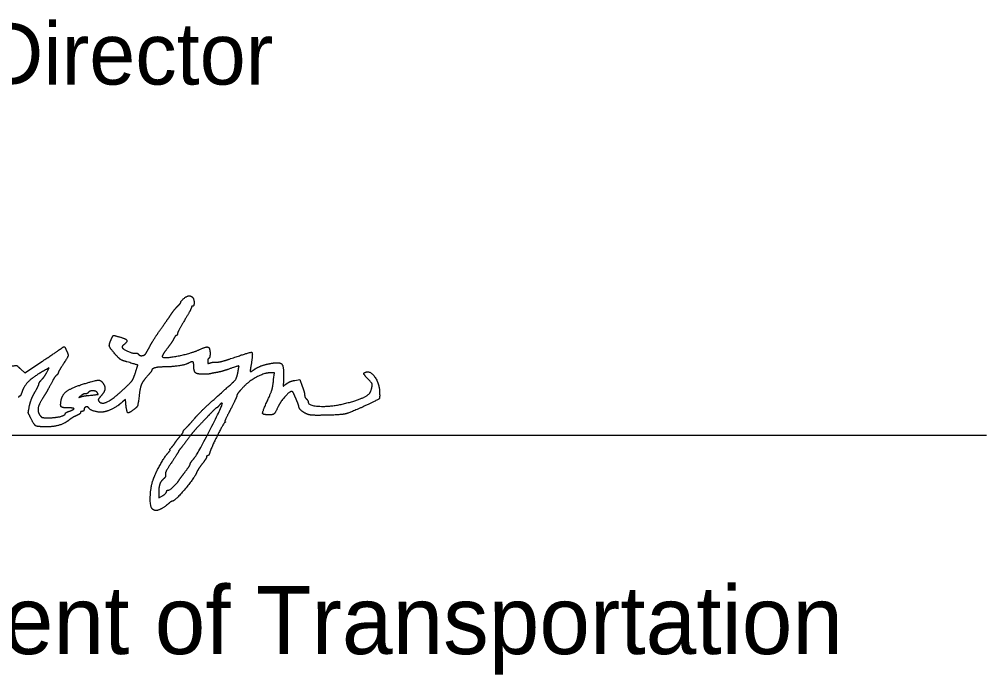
# Model space of a CAD drawing. Extents: x -3.6 to 34, y 0 to 32.8.
# Drawn here: x 26.697 to 28.884, y 4.004 to 5.485 of the extents above; entities that cross this region are included whole.
import ezdxf

# ---------------------------------------------------------------- set-up
doc = ezdxf.new("R2010")
doc.units = 0
doc.layers.add('SH_Data', color=7, linetype='Continuous')
doc.layers.add('SH_Text', color=7, linetype='Continuous')

msp = doc.modelspace()

# ---------------------------------------------------------------- linework, layer by layer
at = {"layer": 'SH_Data'}
msp.add_line((25.0343, 4.5451), (28.8843, 4.5451), dxfattribs=at)
at = {"layer": 'SH_Text'}
for points in [[(26.7, 4.6941), (26.709, 4.6858), (26.7488, 4.7123)], [(26.7593, 4.6883), (26.7642, 4.6971), (26.7581, 4.6938)], [(27.2717, 4.6708), (27.2734, 4.686), (27.2648, 4.686)], [(27.32, 4.669), (27.3306, 4.6708), (27.3362, 4.6558)], [(26.9372, 4.6183), (26.9365, 4.6258), (26.93, 4.6202)], [(27.0118, 4.4135), (27.0118, 4.4032), (27.02, 4.408)]]:
    msp.add_lwpolyline(points, dxfattribs=at)
for points in [[(27.0619, 4.8457), (27.0619, 4.8488), (27.0764, 4.8601), (27.0805, 4.8602)], [(27.0805, 4.8602), (27.0828, 4.8602), (27.086, 4.8588), (27.0878, 4.8571)], [(27.0878, 4.8571), (27.0916, 4.8533), (27.092, 4.8365), (27.0883, 4.8365)], [(27.0395, 4.8178), (27.0438, 4.8242), (27.0507, 4.8327), (27.0547, 4.8367)], [(27.0547, 4.8367), (27.0587, 4.8407), (27.0619, 4.8447), (27.0619, 4.8457)], [(27.0883, 4.8365), (27.0869, 4.8365), (27.0857, 4.8352), (27.0857, 4.8337)], [(27.0157, 4.7837), (27.0244, 4.796), (27.0352, 4.8114), (27.0395, 4.8178)], [(27.0857, 4.8337), (27.0857, 4.8322), (27.0786, 4.8189), (27.0698, 4.8042)], [(27.0698, 4.8042), (27.0611, 4.7894), (27.054, 4.7758), (27.054, 4.7739)], [(26.9035, 4.7598), (26.9076, 4.7697), (26.911, 4.7708), (26.925, 4.7667)], [(26.9922, 4.7467), (26.9964, 4.7547), (27.007, 4.7713), (27.0157, 4.7837)], [(27.0518, 4.7705), (27.0506, 4.7705), (27.048, 4.7672), (27.046, 4.7632)], [(27.054, 4.7739), (27.054, 4.772), (27.053, 4.7705), (27.0518, 4.7705)], [(26.9142, 4.7274), (26.9016, 4.7418), (26.8991, 4.7492), (26.9035, 4.7598)], [(26.925, 4.7667), (26.9382, 4.7628), (26.9413, 4.756), (26.9329, 4.7496)], [(26.9329, 4.7496), (26.9299, 4.7473), (26.9283, 4.7442), (26.9293, 4.7427)], [(27.046, 4.7632), (27.044, 4.7592), (27.0373, 4.7492), (27.0311, 4.741)], [(26.7488, 4.7123), (26.7707, 4.7269), (26.7901, 4.74), (26.7919, 4.7414)], [(26.7919, 4.7414), (26.7969, 4.7456), (26.7995, 4.7446), (26.8028, 4.7374)], [(26.8028, 4.7374), (26.8076, 4.7268), (26.8066, 4.7223), (26.7953, 4.7048)], [(26.94, 4.7108), (26.9282, 4.7142), (26.9228, 4.7177), (26.9142, 4.7274)], [(26.9293, 4.7427), (26.9323, 4.7385), (26.9542, 4.7295), (26.9593, 4.7304)], [(26.9593, 4.7304), (26.9617, 4.7308), (26.9645, 4.7299), (26.9655, 4.7284)], [(26.9655, 4.7284), (26.9678, 4.7245), (26.9789, 4.7249), (26.982, 4.7289)], [(26.982, 4.7289), (26.9834, 4.7307), (26.988, 4.7387), (26.9922, 4.7467)], [(27.0311, 4.741), (27.0248, 4.7328), (27.0197, 4.7248), (27.0197, 4.7233)], [(27.0197, 4.7233), (27.0197, 4.7175), (27.0853, 4.7296), (27.105, 4.739)], [(27.105, 4.739), (27.1193, 4.7458), (27.1279, 4.7423), (27.1279, 4.7298)], [(27.1279, 4.7298), (27.1279, 4.7248), (27.1267, 4.7199), (27.1253, 4.719)], [(27.1745, 4.718), (27.2189, 4.7333), (27.2254, 4.7315), (27.2209, 4.7052)], [(26.7953, 4.7048), (26.7895, 4.6958), (26.7847, 4.6875), (26.7847, 4.6862)], [(26.9585, 4.6846), (26.9647, 4.7031), (26.9643, 4.7037), (26.94, 4.7108)], [(27.0784, 4.7073), (27.0722, 4.704), (27.039, 4.6992), (27.0226, 4.6992)], [(27.091, 4.7021), (27.091, 4.7102), (27.0869, 4.7119), (27.0784, 4.7073)], [(27.1253, 4.719), (27.1238, 4.7181), (27.1226, 4.715), (27.1226, 4.7121)], [(27.1226, 4.7121), (27.1226, 4.7078), (27.1238, 4.7071), (27.1286, 4.7087)], [(27.1286, 4.7087), (27.1318, 4.7097), (27.1383, 4.7104), (27.1428, 4.7103)], [(27.1428, 4.7103), (27.1474, 4.7101), (27.1616, 4.7136), (27.1745, 4.718)], [(27.2209, 4.7052), (27.2194, 4.6968), (27.2186, 4.6895), (27.2191, 4.689)], [(27.2274, 4.6933), (27.2354, 4.6988), (27.2555, 4.7058), (27.2705, 4.7081)], [(27.2705, 4.7081), (27.2866, 4.7107), (27.295, 4.6992), (27.2942, 4.6759)], [(26.6686, 4.7012), (26.6909, 4.7025), (26.6911, 4.7025), (26.7, 4.6941)], [(26.7581, 4.6938), (26.7324, 4.6801), (26.7073, 4.6573), (26.7028, 4.6436)], [(26.7452, 4.6684), (26.7512, 4.675), (26.754, 4.6789), (26.7593, 4.6883)], [(26.7847, 4.6862), (26.7847, 4.685), (26.783, 4.6826), (26.7808, 4.6808)], [(26.9384, 4.6546), (26.9498, 4.6656), (26.9544, 4.6724), (26.9585, 4.6846)], [(26.9959, 4.6913), (26.9959, 4.6903), (26.9913, 4.6844), (26.9856, 4.6781)], [(27.0226, 4.6992), (27.0099, 4.6992), (26.9959, 4.6951), (26.9959, 4.6913)], [(27.1122, 4.6827), (27.0986, 4.6828), (27.091, 4.6897), (27.091, 4.7021)], [(27.1306, 4.6843), (27.1269, 4.6834), (27.1187, 4.6827), (27.1122, 4.6827)], [(27.1451, 4.6871), (27.1407, 4.6864), (27.1342, 4.6852), (27.1306, 4.6843)], [(27.142, 4.6304), (27.181, 4.6652), (27.1886, 4.6741), (27.1913, 4.6887)], [(27.1686, 4.6938), (27.16, 4.6909), (27.1494, 4.6879), (27.1451, 4.6871)], [(27.1913, 4.6887), (27.1936, 4.7014), (27.1917, 4.7018), (27.1686, 4.6938)], [(27.2648, 4.686), (27.2508, 4.686), (27.2137, 4.6658), (27.2003, 4.6508)], [(27.2191, 4.689), (27.2196, 4.6885), (27.2234, 4.6904), (27.2274, 4.6933)], [(27.4812, 4.6765), (27.4754, 4.6828), (27.4751, 4.6857), (27.4802, 4.6876)], [(27.4802, 4.6876), (27.4897, 4.6913), (27.51, 4.6638), (27.5111, 4.6459)], [(26.7315, 4.6419), (26.7364, 4.6503), (26.7406, 4.6587), (26.7408, 4.6607)], [(26.7408, 4.6607), (26.7411, 4.6626), (26.7431, 4.6661), (26.7452, 4.6684)], [(26.7732, 4.6706), (26.7643, 4.6536), (26.7557, 4.6385), (26.749, 4.6278)], [(26.7808, 4.6808), (26.7787, 4.679), (26.7753, 4.6744), (26.7732, 4.6706)], [(26.8324, 4.6577), (26.8675, 4.6693), (26.8822, 4.6698), (26.8878, 4.6594)], [(26.9856, 4.6781), (26.9763, 4.6676), (26.97, 4.6538), (26.9682, 4.6398)], [(27.2556, 4.6182), (27.2655, 4.6401), (27.27, 4.6546), (27.2717, 4.6708)], [(27.2942, 4.6759), (27.2934, 4.6556), (27.2933, 4.6559), (27.3018, 4.662)], [(27.3018, 4.662), (27.3059, 4.6649), (27.3141, 4.6681), (27.32, 4.669)], [(27.4913, 4.6445), (27.4956, 4.6575), (27.4939, 4.6629), (27.4812, 4.6765)], [(26.7028, 4.6436), (26.7009, 4.6379), (26.6984, 4.6332), (26.6972, 4.6332)], [(26.7195, 4.6112), (26.7213, 4.6197), (26.7267, 4.6335), (26.7315, 4.6419)], [(26.7911, 4.6235), (26.7934, 4.6359), (26.8112, 4.6506), (26.8324, 4.6577)], [(26.8458, 4.6385), (26.8432, 4.6385), (26.8389, 4.6366), (26.836, 4.6343)], [(26.8519, 4.6408), (26.8511, 4.6395), (26.8483, 4.6385), (26.8458, 4.6385)], [(26.8722, 4.642), (26.8691, 4.6457), (26.8543, 4.6449), (26.8519, 4.6408)], [(26.8547, 4.635), (26.8731, 4.6367), (26.8757, 4.6378), (26.8722, 4.642)], [(26.8757, 4.6228), (26.8816, 4.6133), (26.9109, 4.6282), (26.9384, 4.6546)], [(26.8878, 4.6594), (26.8914, 4.6527), (26.8876, 4.6402), (26.8794, 4.6315)], [(26.9682, 4.6398), (26.9651, 4.6151), (26.9632, 4.609), (26.957, 4.6041)], [(27.2003, 4.6508), (27.1939, 4.6437), (27.1886, 4.6365), (27.1886, 4.6348)], [(27.3123, 4.6438), (27.3075, 4.6438), (27.2875, 4.6212), (27.2823, 4.61)], [(27.3184, 4.6365), (27.3168, 4.6405), (27.314, 4.6438), (27.3123, 4.6438)], [(27.3362, 4.6558), (27.3392, 4.6476), (27.3418, 4.6387), (27.3418, 4.6359)], [(27.4375, 4.6178), (27.4635, 4.6246), (27.4888, 4.6372), (27.4913, 4.6445)], [(27.5111, 4.6459), (27.5121, 4.6291), (27.5092, 4.6257), (27.4834, 4.6136)], [(26.6972, 4.6332), (26.696, 4.6332), (26.6949, 4.6317), (26.6949, 4.6299)], [(26.749, 4.6278), (26.7402, 4.6139), (26.7378, 4.5972), (26.7434, 4.5897)], [(26.806, 4.6068), (26.7933, 4.6068), (26.7889, 4.6118), (26.7911, 4.6235)], [(26.836, 4.6343), (26.831, 4.6302), (26.831, 4.6302), (26.8362, 4.632)], [(26.8362, 4.632), (26.8391, 4.633), (26.8474, 4.6344), (26.8547, 4.635)], [(26.8794, 4.6315), (26.8764, 4.6283), (26.8747, 4.6244), (26.8757, 4.6228)], [(26.93, 4.6202), (26.9197, 4.6112), (26.8977, 4.5995), (26.8877, 4.5976)], [(26.957, 4.6041), (26.9441, 4.594), (26.9393, 4.5974), (26.9372, 4.6183)], [(27.0906, 4.4912), (27.0991, 4.5008), (27.1576, 4.615), (27.1553, 4.6172)], [(27.0935, 4.5834), (27.1014, 4.5927), (27.1232, 4.6138), (27.142, 4.6304)], [(27.1553, 4.6172), (27.1545, 4.618), (27.1517, 4.616), (27.149, 4.6128)], [(27.1886, 4.6348), (27.1886, 4.633), (27.1821, 4.6189), (27.1741, 4.6034)], [(27.2637, 4.591), (27.2477, 4.591), (27.2459, 4.5969), (27.2556, 4.6182)], [(27.325, 4.6209), (27.323, 4.6255), (27.3201, 4.6325), (27.3184, 4.6365)], [(27.3286, 4.6104), (27.3286, 4.6116), (27.3269, 4.6164), (27.325, 4.6209)], [(27.3418, 4.6359), (27.3418, 4.6332), (27.3435, 4.6292), (27.3457, 4.627)], [(27.3457, 4.627), (27.3479, 4.6248), (27.3497, 4.6218), (27.3497, 4.6204)], [(27.3497, 4.6204), (27.3497, 4.611), (27.4053, 4.6094), (27.4375, 4.6178)], [(26.7217, 4.5848), (26.7168, 4.5948), (26.7166, 4.5973), (26.7195, 4.6112)], [(26.8006, 4.5939), (26.8006, 4.595), (26.8047, 4.5974), (26.8097, 4.5992)], [(26.8097, 4.5992), (26.821, 4.6033), (26.8193, 4.6068), (26.806, 4.6068)], [(26.8349, 4.5962), (26.8349, 4.5947), (26.8322, 4.5923), (26.8289, 4.5908)], [(26.8388, 4.5989), (26.8367, 4.5989), (26.8349, 4.5977), (26.8349, 4.5962)], [(26.8428, 4.6026), (26.8428, 4.6005), (26.841, 4.5989), (26.8388, 4.5989)], [(26.8533, 4.607), (26.851, 4.6106), (26.8428, 4.6071), (26.8428, 4.6026)], [(26.8877, 4.5976), (26.8782, 4.5959), (26.8564, 4.6018), (26.8533, 4.607)], [(27.133, 4.5982), (27.1285, 4.5935), (27.1169, 4.5813), (27.1072, 4.5711)], [(27.1427, 4.6068), (27.1419, 4.6068), (27.1375, 4.603), (27.133, 4.5982)], [(27.149, 4.6128), (27.1464, 4.6095), (27.1435, 4.6068), (27.1427, 4.6068)], [(27.1741, 4.6034), (27.1661, 4.5878), (27.1604, 4.5751), (27.1615, 4.5751)], [(27.2823, 4.61), (27.2759, 4.5964), (27.2707, 4.591), (27.2637, 4.591)], [(27.3459, 4.5932), (27.3381, 4.5969), (27.3288, 4.6061), (27.3286, 4.6104)], [(27.4834, 4.6136), (27.4451, 4.5956), (27.422, 4.5904), (27.3787, 4.5899)], [(26.7566, 4.5638), (26.7374, 4.5639), (26.7297, 4.5685), (26.7217, 4.5848)], [(26.7434, 4.5897), (26.7465, 4.5855), (26.7504, 4.5844), (26.7627, 4.5844)], [(26.8078, 4.5783), (26.7994, 4.5713), (26.7726, 4.5637), (26.7566, 4.5638)], [(26.7627, 4.5844), (26.7781, 4.5844), (26.8006, 4.59), (26.8006, 4.5939)], [(26.8289, 4.5908), (26.8209, 4.5871), (26.8125, 4.5822), (26.8078, 4.5783)], [(27.0732, 4.561), (27.0764, 4.5641), (27.0856, 4.5742), (27.0935, 4.5834)], [(27.1607, 4.5731), (27.1578, 4.5711), (27.13, 4.515), (27.1268, 4.5045)], [(27.1615, 4.5751), (27.1627, 4.5751), (27.1623, 4.5742), (27.1607, 4.5731)], [(27.3787, 4.5899), (27.3623, 4.5897), (27.351, 4.5909), (27.3459, 4.5932)], [(27.0599, 4.5422), (27.0639, 4.5469), (27.0672, 4.5518), (27.0672, 4.553)], [(27.0672, 4.553), (27.0673, 4.5543), (27.0699, 4.5579), (27.0732, 4.561)], [(27.1072, 4.5711), (27.0976, 4.5609), (27.0867, 4.5486), (27.083, 4.5437)], [(27.0487, 4.5276), (27.0509, 4.531), (27.0559, 4.5376), (27.0599, 4.5422)], [(27.083, 4.5437), (27.0742, 4.5316), (27.0626, 4.5165), (27.0593, 4.5125)], [(27.0337, 4.5058), (27.0367, 4.5091), (27.0383, 4.5118), (27.0373, 4.5118)], [(27.0373, 4.5118), (27.0363, 4.5118), (27.0376, 4.514), (27.0401, 4.5166)], [(27.0401, 4.5166), (27.0427, 4.5193), (27.0465, 4.5242), (27.0487, 4.5276)], [(27.0566, 4.5083), (27.0566, 4.5077), (27.0497, 4.4967), (27.0412, 4.4839)], [(27.0593, 4.5125), (27.0578, 4.5108), (27.0566, 4.5089), (27.0566, 4.5083)], [(27.0006, 4.448), (27.007, 4.4643), (27.0259, 4.4972), (27.0337, 4.5058)], [(27.083, 4.4799), (27.083, 4.4814), (27.0865, 4.4864), (27.0906, 4.4912)], [(27.12, 4.4958), (27.12, 4.4943), (27.1153, 4.4869), (27.1096, 4.4793)], [(27.1225, 4.4986), (27.1211, 4.4986), (27.12, 4.4973), (27.12, 4.4958)], [(27.1268, 4.5045), (27.1258, 4.5012), (27.1238, 4.4986), (27.1225, 4.4986)], [(27.0412, 4.4839), (27.0316, 4.4696), (27.0262, 4.4589), (27.027, 4.4559)], [(27.0718, 4.4625), (27.078, 4.4706), (27.083, 4.4784), (27.083, 4.4799)], [(27.1096, 4.4793), (27.1038, 4.4717), (27.0982, 4.4629), (27.097, 4.4598)], [(26.9986, 4.3771), (26.992, 4.3812), (26.9934, 4.4299), (27.0006, 4.448)], [(27.0229, 4.4464), (27.0164, 4.4407), (27.0118, 4.4271), (27.0118, 4.4135)], [(27.027, 4.4559), (27.0277, 4.4531), (27.026, 4.4491), (27.0229, 4.4464)], [(27.0329, 4.4207), (27.035, 4.4194), (27.0533, 4.436), (27.058, 4.4435)], [(27.097, 4.4598), (27.093, 4.449), (27.0477, 4.3956), (27.0426, 4.3956)], [(27.058, 4.4435), (27.0594, 4.4458), (27.0656, 4.4544), (27.0718, 4.4625)], [(27.0296, 4.4174), (27.0303, 4.4199), (27.0318, 4.4214), (27.0329, 4.4207)], [(27.02, 4.408), (27.0246, 4.4106), (27.0289, 4.4148), (27.0296, 4.4174)], [(27.0057, 4.3745), (27.004, 4.3746), (27.0007, 4.3757), (26.9986, 4.3771)], [(27.0344, 4.3906), (27.0276, 4.3843), (27.01, 4.3745), (27.0057, 4.3745)], [(27.0426, 4.3956), (27.0411, 4.3956), (27.0374, 4.3934), (27.0344, 4.3906)]]:
    msp.add_open_spline(points, degree=2, dxfattribs=at)

# ---------------------------------------------------------------- texts
for s, height, p in [('District       Deputy Director', 0.14, (25.0343, 5.3377)), ('Director, Department of Transportation', 0.154, (25.0343, 4.0501))]:
    msp.add_text(s, height=height, dxfattribs=at).set_placement(p)

doc.saveas('drawing.dxf')
